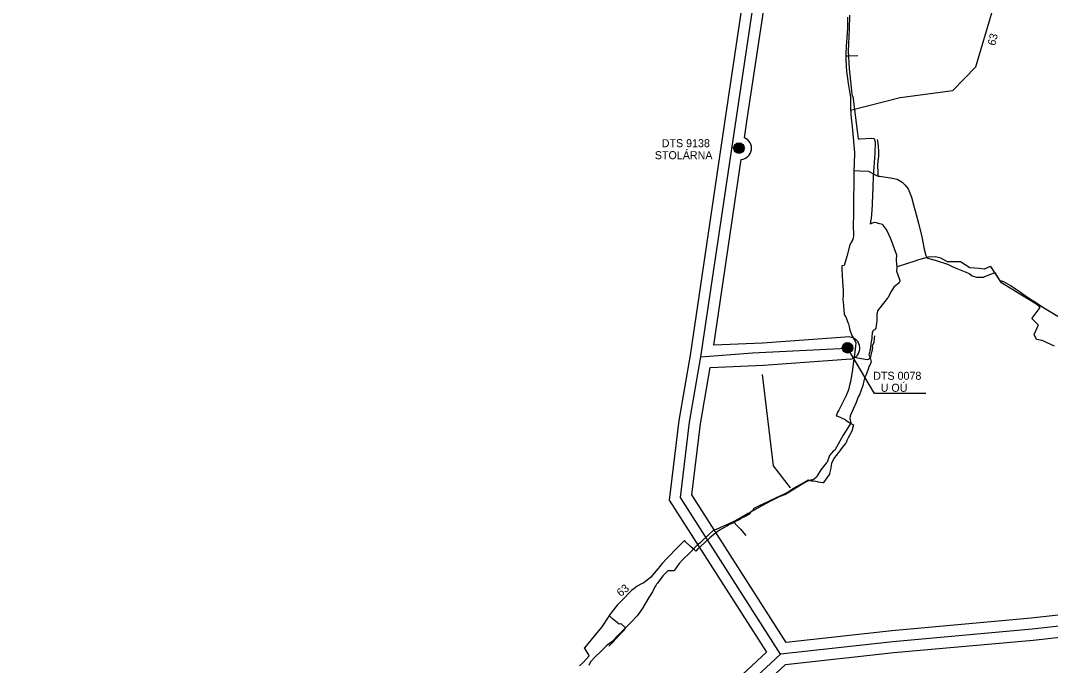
# Model space of a CAD drawing. Extents: x -545241 to -532622, y -1042837 to -1037240.
# Drawn here: x -543445 to -542416, y -1040106 to -1039462 of the extents above; entities that cross this region are included whole.
import ezdxf

# ---------------------------------------------------------------- set-up
doc = ezdxf.new("R2010")
doc.units = 0
for name, color, linetype in [('Vrstva 12', 7, 'Continuous'), ('Vrstva 16', 7, 'Continuous'), ('Vrstva 18', 7, 'Continuous'), ('Vrstva 33', 7, 'Continuous'), ('Vrstva 35', 7, 'Continuous'), ('Vrstva 38', 7, 'Continuous'), ('Vrstva 58', 7, 'Continuous'), ('Vrstva 59', 7, 'Continuous')]:
    doc.layers.add(name, color=color, linetype=linetype)

msp = doc.modelspace()

# ---------------------------------------------------------------- linework, layer by layer
at = {"layer": 'Vrstva 12'}
for centre, radius in [((-542727, -1039589), 5.25), ((-542727, -1039589), 4.55), ((-542727, -1039589), 3.85), ((-542727, -1039589), 3.15), ((-542727, -1039589), 2.45), ((-542727, -1039589), 1.75), ((-542727, -1039589), 1.05), ((-542727, -1039589), 0.35), ((-542618.5, -1039788.6), 5.25), ((-542618.5, -1039788.6), 4.55), ((-542618.5, -1039788.6), 3.85), ((-542618.5, -1039788.6), 3.15), ((-542618.5, -1039788.6), 2.45), ((-542618.5, -1039788.6), 1.75), ((-542618.5, -1039788.6), 1.05), ((-542618.5, -1039788.6), 0.35)]:
    msp.add_circle(centre, radius, dxfattribs=at)
at = {"layer": 'Vrstva 18'}
for points in [[(-542618.6, -1039458), (-542618.7, -1039469.2), (-542619.4, -1039478.8), (-542619.9, -1039487), (-542620.3, -1039494.4), (-542620.3, -1039497.1), (-542620.2, -1039500), (-542620.2, -1039502.5), (-542620, -1039504.8), (-542620, -1039506.9), (-542619.5, -1039512.8), (-542619.3, -1039514.5), (-542618, -1039524.4), (-542616.8, -1039530.5), (-542615.6, -1039538), (-542615.6, -1039542), (-542615.6, -1039544.6), (-542615.6, -1039548.6), (-542615.3, -1039555), (-542615.3, -1039555.3), (-542613.6, -1039571.1), (-542611.7, -1039593.4), (-542612, -1039605), (-542612.3, -1039611.3)], [(-542608.3, -1039496.7), (-542617.8, -1039497), (-542620.3, -1039497.1)], [(-542587.8, -1039617.1), (-542587.9, -1039613.1), (-542588.2, -1039606.2), (-542587.8, -1039601.8), (-542587.1, -1039597.2), (-542587.1, -1039592.2), (-542587.7, -1039587.3), (-542588.4, -1039581.7), (-542588.6, -1039580.4)], [(-542612.3, -1039611.3), (-542612.3, -1039611.5), (-542612.4, -1039611.9), (-542612.4, -1039615), (-542612.3, -1039619.4), (-542612.3, -1039621.9), (-542612.2, -1039624.2), (-542612.5, -1039640.1), (-542612.7, -1039652.4), (-542612.7, -1039656.1), (-542613, -1039665.5), (-542612.6, -1039676.6), (-542612.6, -1039677.2), (-542612.9, -1039679.2), (-542613.6, -1039681), (-542614.5, -1039682.6), (-542615.8, -1039685), (-542616.5, -1039687), (-542619.3, -1039697.5), (-542621.8, -1039706.4), (-542624.1, -1039706.6), (-542624.3, -1039708), (-542624.3, -1039708.1), (-542624.4, -1039708.8), (-542624.3, -1039710.5), (-542623.7, -1039722.2), (-542622.9, -1039731.5), (-542622.8, -1039737.2), (-542623.2, -1039739.2), (-542622.8, -1039743.9), (-542622.7, -1039745.4), (-542622.5, -1039746.9), (-542622.2, -1039750.4), (-542621.8, -1039755.4), (-542621.5, -1039756.1), (-542620.2, -1039757.8), (-542618.1, -1039763.3), (-542617.5, -1039764.7), (-542617.2, -1039766.1), (-542616.1, -1039771.1), (-542613.9, -1039777), (-542610.9, -1039781.9), (-542610.4, -1039783.8), (-542610.6, -1039787.1), (-542612, -1039798.1)], [(-542612.3, -1039611.3), (-542606.3, -1039611.6), (-542597.6, -1039612.1), (-542590.1, -1039616), (-542588, -1039617.1), (-542587.8, -1039617.1), (-542586.5, -1039617.2), (-542575.7, -1039618.7), (-542569, -1039620), (-542563.8, -1039623.2), (-542560.8, -1039626), (-542558, -1039629.8), (-542554.6, -1039638.2), (-542552.5, -1039645.6), (-542550.8, -1039651.7), (-542547.6, -1039664), (-542544.3, -1039677.6), (-542541.8, -1039690), (-542540.2, -1039696.5), (-542539.7, -1039697.7), (-542538.7, -1039698.9), (-542530.8, -1039701.2), (-542518.5, -1039705.2), (-542513.9, -1039707.3), (-542509.2, -1039709.4), (-542500.8, -1039712.8), (-542500, -1039713.1), (-542496.9, -1039714.4), (-542493.9, -1039716.7), (-542489.7, -1039718), (-542484.9, -1039718.1), (-542482.4, -1039717.9), (-542481.5, -1039717.5), (-542481.3, -1039717.5), (-542478.6, -1039716.4), (-542471.2, -1039713.5), (-542471.2, -1039713.5), (-542470.9, -1039713.7), (-542469.2, -1039716.6), (-542467.2, -1039720.1), (-542466.7, -1039720.8), (-542465.9, -1039721.2), (-542462.5, -1039722.3), (-542455.5, -1039726.2), (-542447.8, -1039731.3), (-542440.8, -1039736.2), (-542433.6, -1039741.3), (-542432.6, -1039741.6), (-542423.2, -1039747.9), (-542403.3, -1039759.9)], [(-542591.5, -1039776.6), (-542591.8, -1039778.7), (-542592.4, -1039783.3), (-542593.8, -1039787), (-542593.6, -1039788.5), (-542593.9, -1039789.7), (-542594.3, -1039792.5)], [(-542612, -1039798.1), (-542611.8, -1039798.1), (-542598.9, -1039800.2), (-542597.2, -1039800.1), (-542596.3, -1039799.1), (-542595.4, -1039797.5), (-542594.3, -1039792.5)], [(-542612, -1039798.1), (-542612.2, -1039799.8), (-542613.9, -1039812.7), (-542615.6, -1039822.4), (-542615.6, -1039822.6), (-542616.2, -1039824.8), (-542617.7, -1039830.5), (-542619.9, -1039836.2), (-542624.1, -1039845.1), (-542627.4, -1039851), (-542628.6, -1039853.1), (-542628.7, -1039853.4), (-542629.8, -1039856.6), (-542628.4, -1039857.1), (-542621, -1039860.4), (-542620.7, -1039860.6), (-542617.9, -1039862.7), (-542617.7, -1039862.8), (-542617.2, -1039863), (-542616.3, -1039863.6), (-542615.3, -1039864.2), (-542612.7, -1039865.7), (-542614.4, -1039872.1), (-542618, -1039878.6), (-542619.3, -1039881.3), (-542620, -1039883.6), (-542620, -1039883.7), (-542620.8, -1039884.6), (-542623.8, -1039888.2), (-542627.3, -1039893.1), (-542628.1, -1039894), (-542629.6, -1039895.9), (-542631.8, -1039898.5), (-542634.4, -1039904.4), (-542635.7, -1039910.3), (-542636.4, -1039914.3), (-542636.6, -1039914.9), (-542641, -1039921.1), (-542642.5, -1039923.2), (-542642.9, -1039923.5), (-542643.5, -1039923.5), (-542647.7, -1039922.8), (-542648.7, -1039922.7), (-542650.3, -1039922.3), (-542652.2, -1039922.1), (-542654.1, -1039921.8), (-542655.3, -1039921.6), (-542657.8, -1039921), (-542657.8, -1039921), (-542658.3, -1039921.1), (-542658.7, -1039921.3), (-542667.3, -1039926.4), (-542667.6, -1039926.6), (-542669.1, -1039927.5), (-542669.2, -1039927.6), (-542669.5, -1039927.7), (-542672.9, -1039929.7), (-542675.6, -1039931.4), (-542675.9, -1039931.7), (-542677, -1039932.4), (-542679.9, -1039933.9), (-542682.4, -1039935.3), (-542686.1, -1039937), (-542689.1, -1039938.3), (-542698.3, -1039942.7), (-542706.8, -1039946.6), (-542712.3, -1039949.2), (-542713.7, -1039951.6), (-542714.9, -1039952.4), (-542717, -1039955), (-542717.1, -1039955.1), (-542717.8, -1039955.6), (-542719.7, -1039956.5), (-542722.1, -1039957.9), (-542722.9, -1039958.2), (-542723.2, -1039958.4), (-542725.1, -1039959.4), (-542726.3, -1039960.1), (-542729.9, -1039961.9), (-542731.9, -1039963.1), (-542734.8, -1039964.6), (-542736.4, -1039965.4), (-542738.5, -1039966.5), (-542743.7, -1039969.2), (-542746.7, -1039970.8), (-542750.3, -1039973.7), (-542756.1, -1039978.6), (-542761.6, -1039983.6), (-542768.1, -1039989.5), (-542770.3, -1039991.8), (-542771.5, -1039990.7), (-542772.7, -1039989.7), (-542775.5, -1039987.1), (-542780.7, -1039982.2), (-542780.9, -1039982), (-542781.4, -1039981.4), (-542781.4, -1039981.4), (-542788.6, -1039988.2), (-542798.8, -1039999), (-542799.7, -1040000), (-542803.6, -1040004)], [(-542731.9, -1039963.1), (-542729.1, -1039966.3), (-542725.7, -1039970), (-542720.1, -1039976.3)], [(-542803.6, -1040004), (-542805.9, -1040006.7), (-542806, -1040006.9), (-542808.3, -1040009.6), (-542815.1, -1040018), (-542822.1, -1040023.5), (-542824.4, -1040024.6), (-542828.7, -1040026.8), (-542828.9, -1040027), (-542832.2, -1040029.5), (-542834.4, -1040031.3), (-542844.4, -1040041.7), (-542848.7, -1040046), (-542854, -1040052.3), (-542856.9, -1040056.1), (-542857.2, -1040056.8), (-542864.1, -1040067.6), (-542881.6, -1040088.7), (-542881.7, -1040088.8), (-542881.4, -1040089.2), (-542877.4, -1040095.7), (-542877.3, -1040095.9), (-542876.7, -1040096.6), (-542882.4, -1040102.9), (-542886.4, -1040106.6)], [(-542840.6, -1040068.9), (-542841, -1040068.3), (-542841.3, -1040068), (-542841.3, -1040067.9), (-542844.9, -1040064.5), (-542845, -1040064.7), (-542846.9, -1040064.8), (-542853.4, -1040059.4), (-542856.9, -1040056.1)], [(-542841.7, -1040070.8), (-542842.8, -1040071.9), (-542845.5, -1040074.7), (-542845.7, -1040074.9), (-542853.6, -1040083.1), (-542857, -1040086.5), (-542857.3, -1040086.8)], [(-542841.7, -1040070.8), (-542840.7, -1040069.5), (-542840.6, -1040069), (-542840.6, -1040068.9)]]:
    msp.add_lwpolyline(points, dxfattribs=at)
at = {"layer": 'Vrstva 33'}
for points in [[(-542721.7, -1039578.9), (-542718.9, -1039560), (-542702.6, -1039452.5), (-542692.9, -1039364.3), (-542665.7, -1039123.5), (-542640.9, -1038904.3), (-542628.9, -1038794.4)], [(-542716, -1039372.9), (-542724.4, -1039449.6), (-542740.6, -1039556.7), (-542776, -1039795.9), (-542787.3, -1039861.4), (-542796.9, -1039940.9), (-542699.6, -1040093)], [(-540256.3, -1039496.6), (-540374.9, -1039580.8), (-540487.9, -1039644.3), (-540592.7, -1039662.8), (-540699.7, -1039681.8), (-540817.6, -1039687.7), (-540932.2, -1039696), (-541046.3, -1039703), (-541161.2, -1039710.9), (-541267.3, -1039718), (-541370.9, -1039737.1), (-541467.4, -1039762.4), (-541564.6, -1039787.4), (-541664, -1039813), (-541776, -1039865), (-541888.4, -1039918.2), (-542116.7, -1040029.5), (-542231.8, -1040036.3), (-542435, -1040058.9), (-542574.3, -1040071.4), (-542679.8, -1040083.1)], [(-542752.3, -1039786), (-542724.8, -1039600.3)], [(-542616.3, -1039777.8), (-542703.4, -1039784), (-542752.3, -1039786)], [(-542755.8, -1039808.2), (-542702.5, -1039805.9), (-542615.4, -1039799.8)], [(-542679.8, -1040083.1), (-542774.1, -1039935.7), (-542765.5, -1039864.6), (-542755.8, -1039808.2)], [(-543215.4, -1040605.8), (-543134.2, -1040531.6), (-543044.2, -1040447.5), (-542905.4, -1040315.7), (-542822, -1040236.9), (-542680.6, -1040105.3), (-542572.1, -1040093.3), (-542432.8, -1040080.8), (-542229.9, -1040058.3), (-542111, -1040051.2), (-541878.9, -1039938), (-541766.7, -1039884.9)], [(-542699.6, -1040093), (-542837.1, -1040220.9), (-542920.5, -1040299.7), (-543059.3, -1040431.4), (-543149.1, -1040515.5), (-543230.4, -1040589.7), (-543402.9, -1040753.1), (-543445.3, -1040766.3)]]:
    msp.add_lwpolyline(points, dxfattribs=at)
for centre, start, end in [((-542725.6, -1039589.2), 274.1336, 69.0189), ((-542617.3, -1039788.9), 279.849, 84.8334)]:
    msp.add_arc(centre, 11.1, start, end, dxfattribs=at)
at = {"layer": 'Vrstva 35'}
for points in [[(-542615.5, -1039551.2), (-542566, -1039538.4), (-542513.2, -1039531.6), (-542490.2, -1039507.7), (-542473.2, -1039450.6), (-542446.8, -1039394.4), (-542432.3, -1039373.1)], [(-542675.5, -1039928.6), (-542692.5, -1039906.5), (-542703.6, -1039815.3)]]:
    msp.add_lwpolyline(points, dxfattribs=at)
at = {"layer": 'Vrstva 38'}
msp.add_line((-542734.4, -1039588.1), (-542727, -1039589), dxfattribs=at)
for points in [[(-542685.4, -1040094.8), (-542785.5, -1039938.3), (-542776.4, -1039863), (-542765.2, -1039797.6), (-542729.7, -1039558.4), (-542713.5, -1039451), (-542703.8, -1039363.1), (-542676.6, -1039122.3), (-542651.9, -1038903.1), (-542638.6, -1038781.9), (-542626.2, -1038694), (-542607.4, -1038571.6), (-542574.6, -1038354.5), (-542701.6, -1038169), (-542751.4, -1038094.3), (-542888.7, -1037892.1), (-543053.4, -1037650.3), (-543107.9, -1037569.9)], [(-542765.2, -1039797.6), (-542713.4, -1039793.5), (-542619.3, -1039789.1)], [(-541771.3, -1039874.9), (-541883.7, -1039928.1), (-542113.9, -1040040.3), (-542230.8, -1040047.3), (-542433.9, -1040069.9), (-542573.2, -1040082.4), (-542685.4, -1040094.8), (-542829.5, -1040228.9), (-542913, -1040307.7), (-543051.7, -1040439.5), (-543141.7, -1040523.6), (-543222.9, -1040597.8)]]:
    msp.add_lwpolyline(points, dxfattribs=at)
at = {"layer": 'Vrstva 58'}
for points in [[(-542616.5, -1039456.2), (-542616.8, -1039470.1), (-542618, -1039492.1), (-542617, -1039509.5), (-542615, -1039528.5), (-542614.2, -1039535.1), (-542614, -1039536.8), (-542613.2, -1039537.3), (-542608.8, -1039571.8), (-542608, -1039579.6), (-542606.6, -1039579.6), (-542594.2, -1039579), (-542591.8, -1039579.5), (-542590.8, -1039582.9), (-542591.4, -1039594.1), (-542593, -1039617.4), (-542593.1, -1039627.9), (-542594.3, -1039652.4), (-542594.5, -1039654.2), (-542594.7, -1039656), (-542595.4, -1039661.2), (-542596, -1039664.8), (-542591.6, -1039663.2), (-542589.8, -1039663.5), (-542588, -1039663.9), (-542583.6, -1039665), (-542583.1, -1039665.9), (-542579.4, -1039671.3), (-542575.5, -1039679.3), (-542569.7, -1039695.8), (-542569.9, -1039700.6), (-542569.5, -1039705.5), (-542569.1, -1039707.7)], [(-542411.7, -1039787), (-542423.9, -1039781.4), (-542429.5, -1039780.5), (-542431.9, -1039775.2), (-542431.7, -1039774.7), (-542428.1, -1039766.2), (-542427.9, -1039765.7), (-542434.4, -1039759.5), (-542434.1, -1039759.1), (-542427.1, -1039749.7), (-542426, -1039747.9), (-542430.2, -1039744.7), (-542434.7, -1039741.9), (-542446.2, -1039734.9), (-542464.7, -1039723.7), (-542475.2, -1039707.4), (-542476.5, -1039707.6), (-542481.9, -1039709.9), (-542486.9, -1039709.5), (-542496.2, -1039708.6), (-542505.5, -1039702.6), (-542518.6, -1039702.7), (-542525.4, -1039699.2), (-542530.7, -1039697.7), (-542537.9, -1039698), (-542546.3, -1039700.4), (-542548.5, -1039701.1), (-542551.3, -1039702.1), (-542568, -1039707.3), (-542569.1, -1039707.7)], [(-542569.1, -1039707.7), (-542569.4, -1039708.5), (-542569.6, -1039711.8), (-542569.5, -1039712.1), (-542566.5, -1039720.3), (-542566.2, -1039721.1), (-542566.3, -1039722.1), (-542566.9, -1039723.7), (-542572.4, -1039727.9), (-542575, -1039732.2), (-542578.4, -1039738.8), (-542578.9, -1039739.5), (-542588.6, -1039751.8), (-542589, -1039754.1), (-542589.1, -1039754.9), (-542589.1, -1039758.7), (-542589.1, -1039761.2), (-542589.6, -1039763.9), (-542590.3, -1039768.9), (-542590.8, -1039770.1), (-542591.7, -1039770.7), (-542593, -1039771.5), (-542593.4, -1039772.3), (-542593.8, -1039773.2), (-542594.2, -1039778.1), (-542594.3, -1039778.7), (-542594.4, -1039779.2), (-542594.8, -1039782.3), (-542595.6, -1039787.6), (-542596.4, -1039791.9), (-542596.7, -1039793.3), (-542597.2, -1039795.7), (-542596.3, -1039797.8), (-542595.6, -1039800), (-542594.9, -1039802.8), (-542596.2, -1039806), (-542597.2, -1039807.4), (-542597.7, -1039809.1), (-542599.7, -1039814.7), (-542600.3, -1039816.4), (-542601.6, -1039818.9), (-542602.1, -1039821.7), (-542603.4, -1039826.4), (-542606.6, -1039835.7), (-542607.8, -1039837.6), (-542609.9, -1039843.2), (-542615.9, -1039856.8), (-542616.2, -1039859.3), (-542615.4, -1039864.1), (-542617.3, -1039867), (-542620.5, -1039872.2), (-542622.9, -1039875.8), (-542631.2, -1039891), (-542632.6, -1039891.6), (-542634.9, -1039894.3), (-542636.7, -1039896.2), (-542639, -1039902.9), (-542639.8, -1039904.1), (-542645.3, -1039910.6), (-542648.9, -1039916.7), (-542649.7, -1039918.1), (-542651.5, -1039919.7), (-542651.9, -1039920), (-542657.1, -1039921.7), (-542659.9, -1039922.6), (-542663.8, -1039924.9), (-542667.5, -1039927.2), (-542676.2, -1039932.7), (-542681.2, -1039935.6), (-542682.5, -1039936.1), (-542687.4, -1039937.9), (-542695.5, -1039941.9), (-542704.1, -1039946.6), (-542717.9, -1039954.2), (-542730.5, -1039961.6), (-542730.8, -1039961.7), (-542738, -1039965), (-542742.7, -1039966.8), (-542749.8, -1039970.3), (-542752.4, -1039970.8), (-542757.5, -1039975.6), (-542764.9, -1039982.5), (-542766.3, -1039983.8), (-542767.5, -1039984.9), (-542768.3, -1039985.5), (-542769.2, -1039986.3), (-542771.4, -1039988.7), (-542775.6, -1039992.8), (-542776.3, -1039993.5), (-542783.2, -1040000.4), (-542786.7, -1040004.3), (-542791.4, -1040010.9), (-542792, -1040011.5), (-542798.1, -1040011.7), (-542800.1, -1040013.6), (-542800.8, -1040014.2), (-542803.3, -1040016.6)], [(-542803.3, -1040016.6), (-542808.6, -1040023.9), (-542809.2, -1040024.7), (-542809.4, -1040025), (-542810.2, -1040026.2), (-542811, -1040027.3), (-542811.2, -1040027.6), (-542813.6, -1040032.4), (-542817.2, -1040038.3), (-542823.9, -1040049.6), (-542828.8, -1040056.4), (-542835.2, -1040063.1), (-542839.3, -1040067.2), (-542839.9, -1040067.8), (-542840.5, -1040068.4), (-542841, -1040069), (-542843.6, -1040071.5), (-542847.6, -1040075.6), (-542854.2, -1040082.5), (-542858.7, -1040086), (-542862.4, -1040089.6), (-542865.8, -1040092.8), (-542870.4, -1040097.3), (-542875.6, -1040102.6), (-542877.3, -1040106.3)]]:
    msp.add_lwpolyline(points, dxfattribs=at)
at = {"layer": 'Vrstva 59'}
msp.add_lwpolyline([(-542540.2, -1039834.2), (-542591.5, -1039834.2), (-542618.5, -1039788.6)], dxfattribs=at)

# ---------------------------------------------------------------- texts
at = {"layer": 'Vrstva 16'}
for rotation, p in [(75.9609, (-542471, -1039487.1)), (40.0364, (-542845.2, -1040037.9))]:
    msp.add_text('63', height=8, rotation=rotation, dxfattribs=at).set_placement(p)
at = {"layer": 'Vrstva 59'}
for s, p in [('DTS 9138', (-542804.3, -1039588.1)), ('STOLÁRNA', (-542811.2, -1039600.1)), ('DTS 0078', (-542592.9, -1039820.6)), ('U OÚ', (-542585.4, -1039832.6))]:
    msp.add_text(s, height=8, dxfattribs=at).set_placement(p)

doc.saveas('drawing.dxf')
